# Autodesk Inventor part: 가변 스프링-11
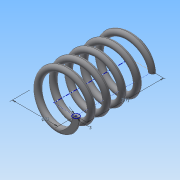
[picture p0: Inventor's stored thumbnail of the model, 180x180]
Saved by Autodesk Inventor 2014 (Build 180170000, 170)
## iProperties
Created: 2015-09
Part Number: 가변 스프링-11
Material: 강철, 탄소
Document SubType Name: Modeling
Designer: study
Density: 1 g/cm^3
Appearance: 반연마
Mass: 2.38851 g
Surface Area: 32.4648 cm^2
Volume: 2.38851 cm^3
Author: study
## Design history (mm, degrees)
sketch "스케치1"
  geometry: L1 (0, 0)-(11, 0); L2 (11, 0)-(11, 36.411); L3 (11, 36.411)-(0, 36.411); L4 (0, 36.411)-(0, 0); C1 r 1.5 at (11, 0)
  constraints: 8 end point, 2 parallel, 1 centre point, 1 coincident, 1 horizontal, 1 perpendicular
  dimensions: "d0" = 36.4112 distance of L1.end L2.end (derived); "d1" = 22 diameter of L1.end L4; "d2" = 3 diameter of C1
feature "코일1" sketch "스케치1" pitch "d3" = 10; turns "d5" = 5; dims "d4" = 36.4112 (= d0), "d6" = 0, angle "d7" = 90 deg, angle "d8" = 90 deg, "d9" = 0, "d10" = 0
node "작업 평면1"
sketch "스케치2"
  geometry: L1 (-12.5, 0)-(-9.5, 0) reference; 1 further point
  constraints: 1 horizontal alignment
extrude "돌출1" cut sketch "스케치2" stored distance "d12" = 10; taper "d13" = 0 deg
node "작업 평면2"
sketch "스케치3"
  geometry: L1 (-9.5, 0)-(-12.5, 0) reference; 1 further point
  constraints: 1 horizontal alignment
extrude "돌출2" cut sketch "스케치3" stored distance "d15" = 10; taper "d16" = 0 deg
node "솔리드1"
node "절단 모서리 투영1"
node "절단 모서리 투영2"
other parameters: "d11" = 0, "d14" = 36.4112 (= d0)
